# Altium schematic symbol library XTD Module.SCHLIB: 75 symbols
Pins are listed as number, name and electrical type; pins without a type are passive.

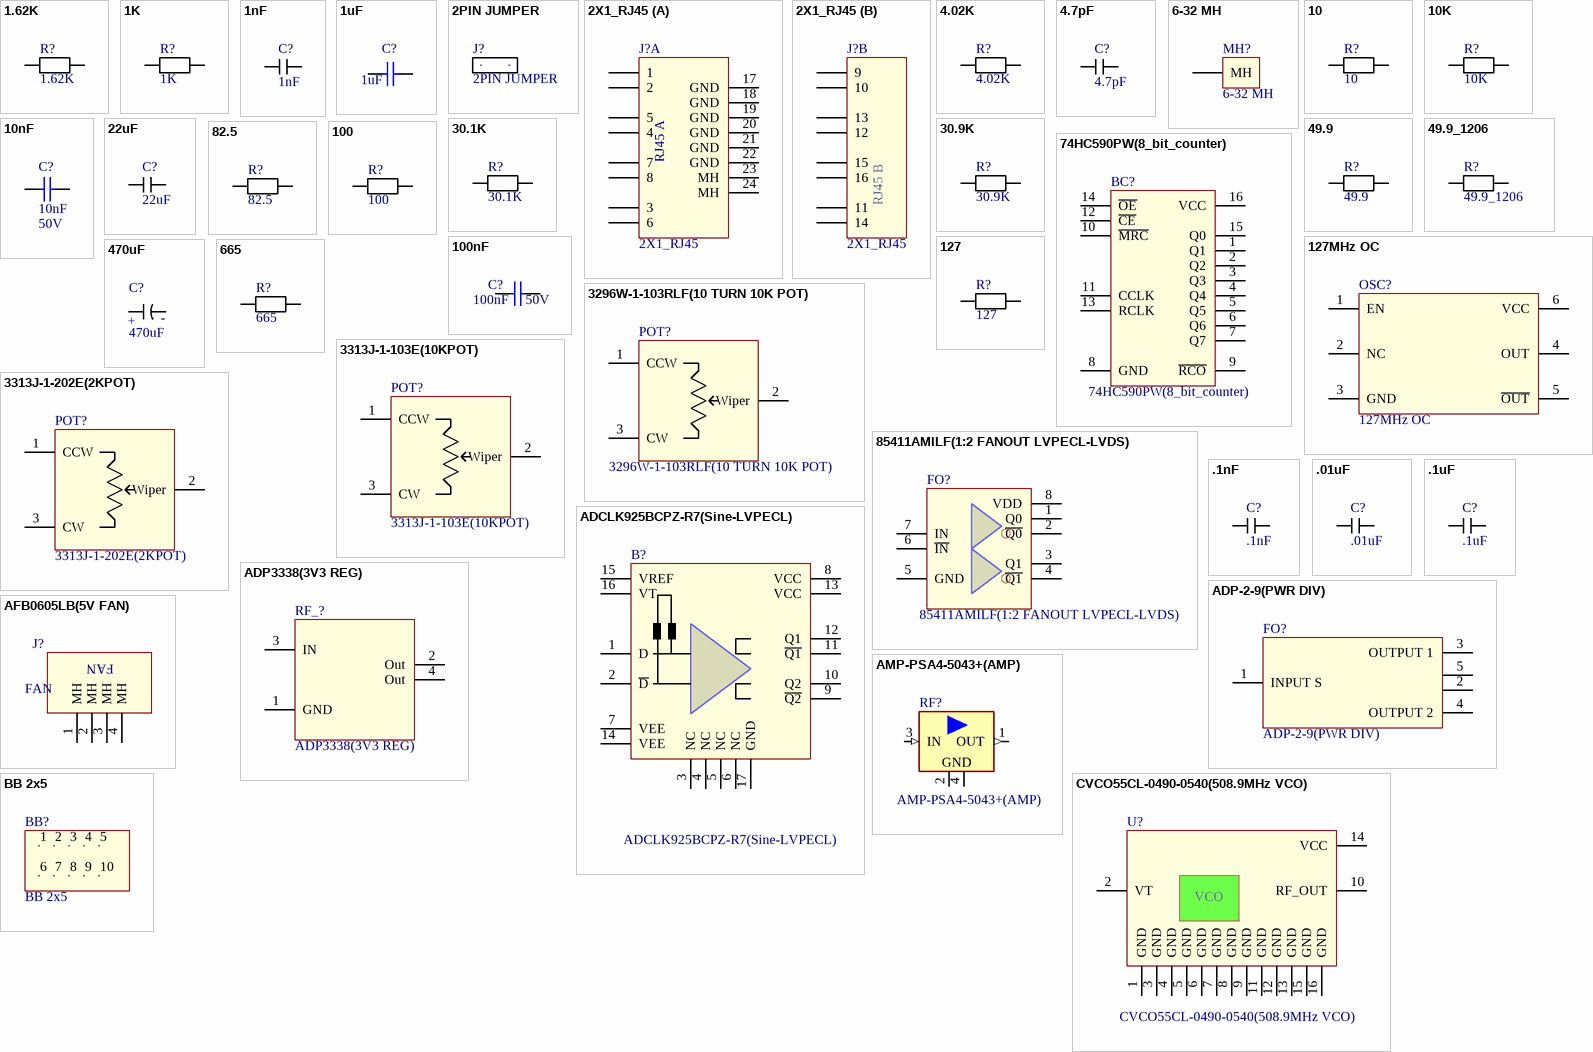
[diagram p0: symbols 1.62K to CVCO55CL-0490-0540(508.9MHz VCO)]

## 1.62K
designator R?
RES SMD 1.62K OHM 1% 1/16W 0402; Manufacturer: Samsung Electro-Mechanics America, Inc.; Manufacturer part #: RC1005F1621CS
footprint 0402 (0.039" L x 0.020" W (1.00mm x 0.50mm))
pins: 1, 2

## 1K
designator R?
RES SMD 1K OHM 5% 1/16W 0402; Manufacturer: Samsung Electro-Mechanics America, Inc.; Manufacturer part #: RC1005J102CS
footprint 0402 (0.039" L x 0.020" W (1.00mm x 0.50mm))
pins: 1, 2

## 1nF
designator C?
CAP CER 1000PF 50V X7R 0402; Manufacturer: Samsung Electro-Mechanics America, Inc.; Manufacturer part #: CL05B102KB5NNNC
footprint 0402 (0.039" L x 0.020" W (1.00mm x 0.50mm))
pins: 1, 2

## 1uF
designator C?
CAP CER 1UF 25V X7R 0603; Tech: SMDR; Voltage rating: 50V
signal-integrity model Model Name (Model Description)
footprint 0603 (0.063" L x 0.031" W (1.60mm x 0.80mm))
pins: 1, 2

## 2PIN JUMPER
designator J?
TWO PIN JUMPER
footprint 2 PIN HEADER
pins: 1, 2

## 2X1_RJ45
designator J?
CONN MOD JACK 8P8C R/A SHIELDED; Manufacturer: EDAC Inc.; Manufacturer part #: A00-216-672-450
footprint 2X1 RJ45 (DOUBLE_RIGHT ANGLE_RJ-45)
part A pins: 1, 2, 3, 4, 5, 6, 7, 8, 17 GND, 18 GND, 19 GND, 20 GND, 21 GND, 22 GND, 23 MH, 24 MH
part B pins: 9, 10, 11, 12, 13, 14, 15, 16

## 4.02K
designator R?
RES SMD 4.02K OHM 1% 1/16W 0402; Manufacturer: Samsung Electro-Mechanics America, Inc.; Manufacturer part #: RC1005F4021CS
footprint 0402 (0.039" L x 0.020" W (1.00mm x 0.50mm))
pins: 1, 2

## 4.7pF
designator C?
CAP CER 4.7PF 50V NP0 0603; Manufacturer: Samsung Electro-Mechanics America, Inc.; Manufacturer part #: CL10C4R7CB8NNNC
footprint 0603 (0.063" L x 0.031" W (1.60mm x 0.80mm))
pins: 1 "GROUND", 2

## 6-32 MH
designator MH?
6-32 MOUNTING HOLE
footprint 6-32 MH (6-32 MOUNTING HOLE)
pins: 1 MH

## 10
designator R?
RES SMD 10 OHM 5% 1/16W 0402; Manufacturer: Samsung Electro-Mechanics America, Inc.; Manufacturer part #: RC1005J100CS
footprint 0402 (0.039" L x 0.020" W (1.00mm x 0.50mm))
pins: 1, 2

## 10K
designator R?
RES SMD 10K OHM 5% 1/16W 0402; Manufacturer: Samsung Electro-Mechanics America, Inc.; Manufacturer part #: RC1005F4021CS
footprint 0402 (0.039" L x 0.020" W (1.00mm x 0.50mm))
pins: 1, 2

## 10nF
designator C?  Voltage rating: 50V
CAP CER 10000PF 50V X7R 0402; Manufacturer: Murata; Manufacturer No: GRM155R71H103KA88D; Tech: SMDR
footprint 0402 (0.039" L x 0.020" W (1.00mm x 0.50mm))
pins: 1, 2

## 22uF
designator C?
CAP CER 22UF 6.3V X5R 0603; Manufacturer: Samsung Electro-Mechanics America, Inc.; Manufacturer part #: CL10A226KQ8NRNE
footprint 0603 (0.063" L x 0.031" W (1.60mm x 0.80mm))
pins: 1 "GROUND", 2

## 30.1K
designator R?
RES SMD 30.1K OHM 1% 1/16W 0402; Manufacturer: Samsung Electro-Mechanics America, Inc.; Manufacturer part #: RC1005F3012CS
footprint 0402 (0.039" L x 0.020" W (1.00mm x 0.50mm))
pins: 1, 2

## 30.9K
designator R?
RES SMD 30.9K OHM 1% 1/10W 0402; Manufacturer: Panasonic Electronic Components; Manufacturer part #: ERJ-2RKF3092X
footprint 0402 (0.039" L x 0.020" W (1.00mm x 0.50mm))
pins: 1, 2

## 49.9
designator R?
RES SMD 49.9 OHM 1% 1/16W 0402; Manufacturer: Samsung Electro-Mechanics America, Inc.; Manufacturer part #: RC1005F49R9CS
footprint 0402 (0.039" L x 0.020" W (1.00mm x 0.50mm))
pins: 1, 2

## 49.9_1206
designator R?
RES SMD 49.9 OHM 1% 1/2W 1206; Manufacturer: Stackpole Electronics Inc.; Manufacturer part #: RNCP1206FTD49R9
footprint RC1206N1X (Chip resistor 1206)
pins: 1, 2

## 74HC590PW(8_bit_counter)
designator BC?
IC BINARY COUNTER 8BIT 16-TSSOP; Manufacturer: NXP Semiconductors; Manufacturer part #: 74HC590PW,118
footprint TSSOP_16pin (TSOP, 16-Leads, Body 5.00x4.40mm, Pitch 0.65mm, IPC Medium Density)
pins: 1 Q1, 2 Q2, 3 Q3, 4 Q4, 5 Q5, 6 Q6, 7 Q7, 8 GND, 9 ~{RCO}, 10 ~{MRC}, 11 CCLK, 12 ~{CE}, 13 RCLK, 14 ~{OE}, 15 Q0, 16 VCC

## 82.5
designator R?
RES SMD 82.5 OHM 1% 1/16W 0402; Manufacturer: Samsung Electro-Mechanics America, Inc.; Manufacturer part #: RC1005F82R5CS
footprint 0402 (0.039" L x 0.020" W (1.00mm x 0.50mm))
pins: 1, 2

## 100
designator R?
RES SMD 100 OHM 5% 1/16W 0402; Manufacturer: Samsung Electro-Mechanics America, Inc.; Manufacturer part #: RC1005J101CS
footprint 0402 (0.039" L x 0.020" W (1.00mm x 0.50mm))
pins: 1, 2

## 100nF
designator C?  Voltage rating: 50V
Capacitor chip ceramic 0402 50V X7R; Manufacturer: TDK; Manufacturer No: C1005X7R1H104K050BB; Tech: SMDR
signal-integrity model Model Name (Model Description)
footprint 0402 (0.039" L x 0.020" W (1.00mm x 0.50mm))
pins: 1, 2

## 127
designator R?
RES SMD 127 OHM 1% 1/16W 0402; Manufacturer: Samsung Electro-Mechanics America, Inc.; Manufacturer part #: RC1005F1270CS
footprint 0402 (0.039" L x 0.020" W (1.00mm x 0.50mm))
pins: 1, 2

## 127MHz OC
designator OSC?
OSC VCO 127.21MHZ
footprint 127MHz OC
pins: 1 EN "ENABLE/DISABLE", 2 NC, 3 GND "GROUND", 4 OUT "NONEINVERTED OUTPUT", 5 ~{OUT} "INVERTED OUTPUT", 6 VCC "POWER INPUT"

## 470uF
designator C?
CAP ALUM 470UF 20% 50V RADIAL; Manufacturer: Nichicon; Manufacturer part #: UPW1H471MHD
footprint CAP_TH
pins: 1 "GROUND", 2

## 665
designator R?
RES SMD 665 OHM 1% 1/16W 0402; Manufacturer: Samsung Electro-Mechanics America, Inc.; Manufacturer part #: RC1005F6650CS
footprint 0402 (0.039" L x 0.020" W (1.00mm x 0.50mm))
pins: 1, 2

## 3296W-1-103RLF(10 TURN 10K POT)
designator POT?
TRIMMER 10K OHM 0.5W PC PIN; Manufacturer: Bourns Inc.
footprint 10K POT (TRIMMER 10K OHM 0.5W PC PIN)
pins: 1 CCW "Control Votage", 2 Wiper "Ground", 3 CW "Supply Voltage"

## 3313J-1-103E(10KPOT)
designator POT?
TRIMMER 10K OHM 0.125W SMD; Manufacturer: Bourns Inc.
footprint 2KPOT (TRIMMER 2K OHM 0.125W SMD)
pins: 1 CCW "Control Votage", 2 Wiper "Ground", 3 CW "Supply Voltage"

## 3313J-1-202E(2KPOT)
designator POT?
TRIMMER 2K OHM 0.125W SMD; Manufacturer: Bourns Inc.
footprint 2KPOT (TRIMMER 2K OHM 0.125W SMD)
pins: 1 CCW "Control Votage", 2 Wiper "Ground", 3 CW "Supply Voltage"

## 85411AMILF(1:2 FANOUT LVPECL-LVDS)
designator FO?
IC CLK BUFFER 1:2 650MHZ 8SOIC; Manufacturer: IDT, Integrated Device Technology Inc
footprint SOIC_8pin (SOIC, 8-Leads, Body 5.00x4.00mm, Pitch 1.27mm, IPC Medium Density)
pins: 1 Q0, 2 ~{Q0}, 3 Q1, 4 ~{Q1}, 5 GND, 6 ~{IN}, 7 IN, 8 VDD

## .1nF
designator C?
CAP CER 100PF 50V NP0 0603; Manufacturer: Samsung Electro-Mechanics America, Inc.; Manufacturer part #: CL10C101JB8NNNC
footprint 0603 (0.063" L x 0.031" W (1.60mm x 0.80mm))
pins: 1 "GROUND", 2

## .01uF
designator C?
CAP CER 10000PF 50V X7R 0603; Manufacturer: Samsung Electro-Mechanics America, Inc.; Manufacturer part #: CL10B103KB8NCNC
footprint 0603 (0.063" L x 0.031" W (1.60mm x 0.80mm))
pins: 1 "GROUND", 2

## .1uF
designator C?
CAP CER 0.1UF 50V X7R 0603; Manufacturer: Samsung Electro-Mechanics America, Inc.; Manufacturer part: CL10B104KB8SFNC
footprint 0603 (0.063" L x 0.031" W (1.60mm x 0.80mm))
pins: 1 "GROUND", 2

## ADCLK925BCPZ-R7(Sine-LVPECL)
designator B?
IC CLK BUFFER 1:2 7.5GHZ 16LFCSP; Manufacturer: Analog Devices Inc.
footprint QFN_16pin (QFN, 16-Leads, Body 3.00x3.00mm, Pitch 0.50mm, Thermal Pad 1.50x1.50mm, IPC Medium Density)
pins: 1 D "Noninverting Input", 2 ~{D} "Inverting Input", 3 NC "No Connect", 4 NC "No Connect", 5 NC "No Connect", 6 NC "No Connect", 7 VEE "Negative Supply Voltage.", 8 VCC "Positive Supply Voltage.", 9 ~{Q2} "Inverting Output 2.", 10 Q2 "Noninverting Output 2.", 11 ~{Q1} "Inverting Output 1.", 12 Q1 "Noninverting Output 1.", 13 VCC "Positive Supply Voltage.", 14 VEE "Negative Supply Voltage.", 15 VREF "Reference Voltage.", 16 VT "Center Tap. Center tap of 100 Ω input resistor.", 17 GND "Center Tap. Center tap of 100 Ω input resistor."

## ADP3338(3V3 REG)
designator RF_?
IC REG LDO 3.3V 1A SOT223-3; Manufacturer: Analog Devices Inc; Manufacturer part #: ADP3338AKCZ-3.3RL7
footprint ADP3338 (SOT223, 4-Leads, Body 6.50x7.00mm (avg), Pitch 2.30mm, IPC Medium Density)
footprint ADP3338 (SOT223, 4-Leads, Body 6.50x7.00mm (avg), Pitch 2.30mm, IPC Medium Density)
pins: 1 GND "Ground", 2 Out "Output", 3 IN "Input", 4 Out "Output"

## ADP-2-9(PWR DIV)
designator FO?
PWR SPL CMB / SM / RoHS5; Manufacturer: MINI_CIRCUITS
footprint PWR SPLITTER (SOTFL, 6-Leads, Body 7.87x6.91mm, Pitch 2.54mm, IPC Medium Density)
pins: 1 INPUT S "INPUT", 2 OUTPUT 4 "Externally connect together & isolate", 3 OUTPUT 1 "OUTPUT", 4 OUTPUT 2 "OUTPUT", 5 OUTPUT 3 "Externally connect together & isolate"

## AFB0605LB(5V FAN)
designator J?, comment FAN
FAN AXIAL 60X15MM BALL 5VDC WIRE; Manufacturer: Delta Electronics; Manufacturer part #: AFB0605LB
footprint FAN (FAN AXIAL 60X15MM BALL 5VDC WIRE)
pins: 1 MH, 2 MH, 3 MH, 4 MH

## AMP-PSA4-5043+(AMP)
designator RF?
Monolithic Amplifier 50MHz - 4GHz, 0.75NF; Manufacturer: MiniCircuits; Tech: SMDR
footprint MMM1362
pins: 1 OUT (out), 2 GND (power), 3 IN (in), 4 GND (power)

## BB 2x5
designator BB?
footprint BREAD BOARD (2X5 .1IN BREAD BAORD)
pins: 1 "POSITIVE GROUND", 2 "POSITIVE GROUND", 3 "POSITIVE GROUND", 4 "POSITIVE GROUND", 5 "POSITIVE GROUND", 6 "POSITIVE GROUND", 7 "POSITIVE GROUND", 8 "POSITIVE GROUND", 9 "POSITIVE GROUND", 10 "POSITIVE GROUND"

## CVCO55CL-0490-0540(508.9MHz VCO)
designator U?
OSC VCO 490-540MHZ SMD .5X.5"; Manufacturer: ON Semiconductor
footprint QFN_16pin Variant (QFN, 16-Leads, Body 12.70x12.70mm, Pitch 2.54mm, Variant)
pins: 1 GND "Regulator Input Supply.", 2 VT "Control voltage", 3 GND "Regulator Input Supply.", 4 GND "Regulator Input Supply.", 5 GND "Regulator Input Supply.", 6 GND "Regulator Input Supply.", 7 GND "Regulator Input Supply.", 8 GND "Regulator Input Supply.", 9 GND "Regulator Input Supply.", 10 RF_OUT "RF OUTPUT", 11 GND "Regulator Input Supply.", 12 GND "Regulator Input Supply.", 13 GND "Regulator Input Supply.", 14 VCC "Positive power pin", 15 GND "Regulator Input Supply.", 16 GND "Regulator Input Supply."

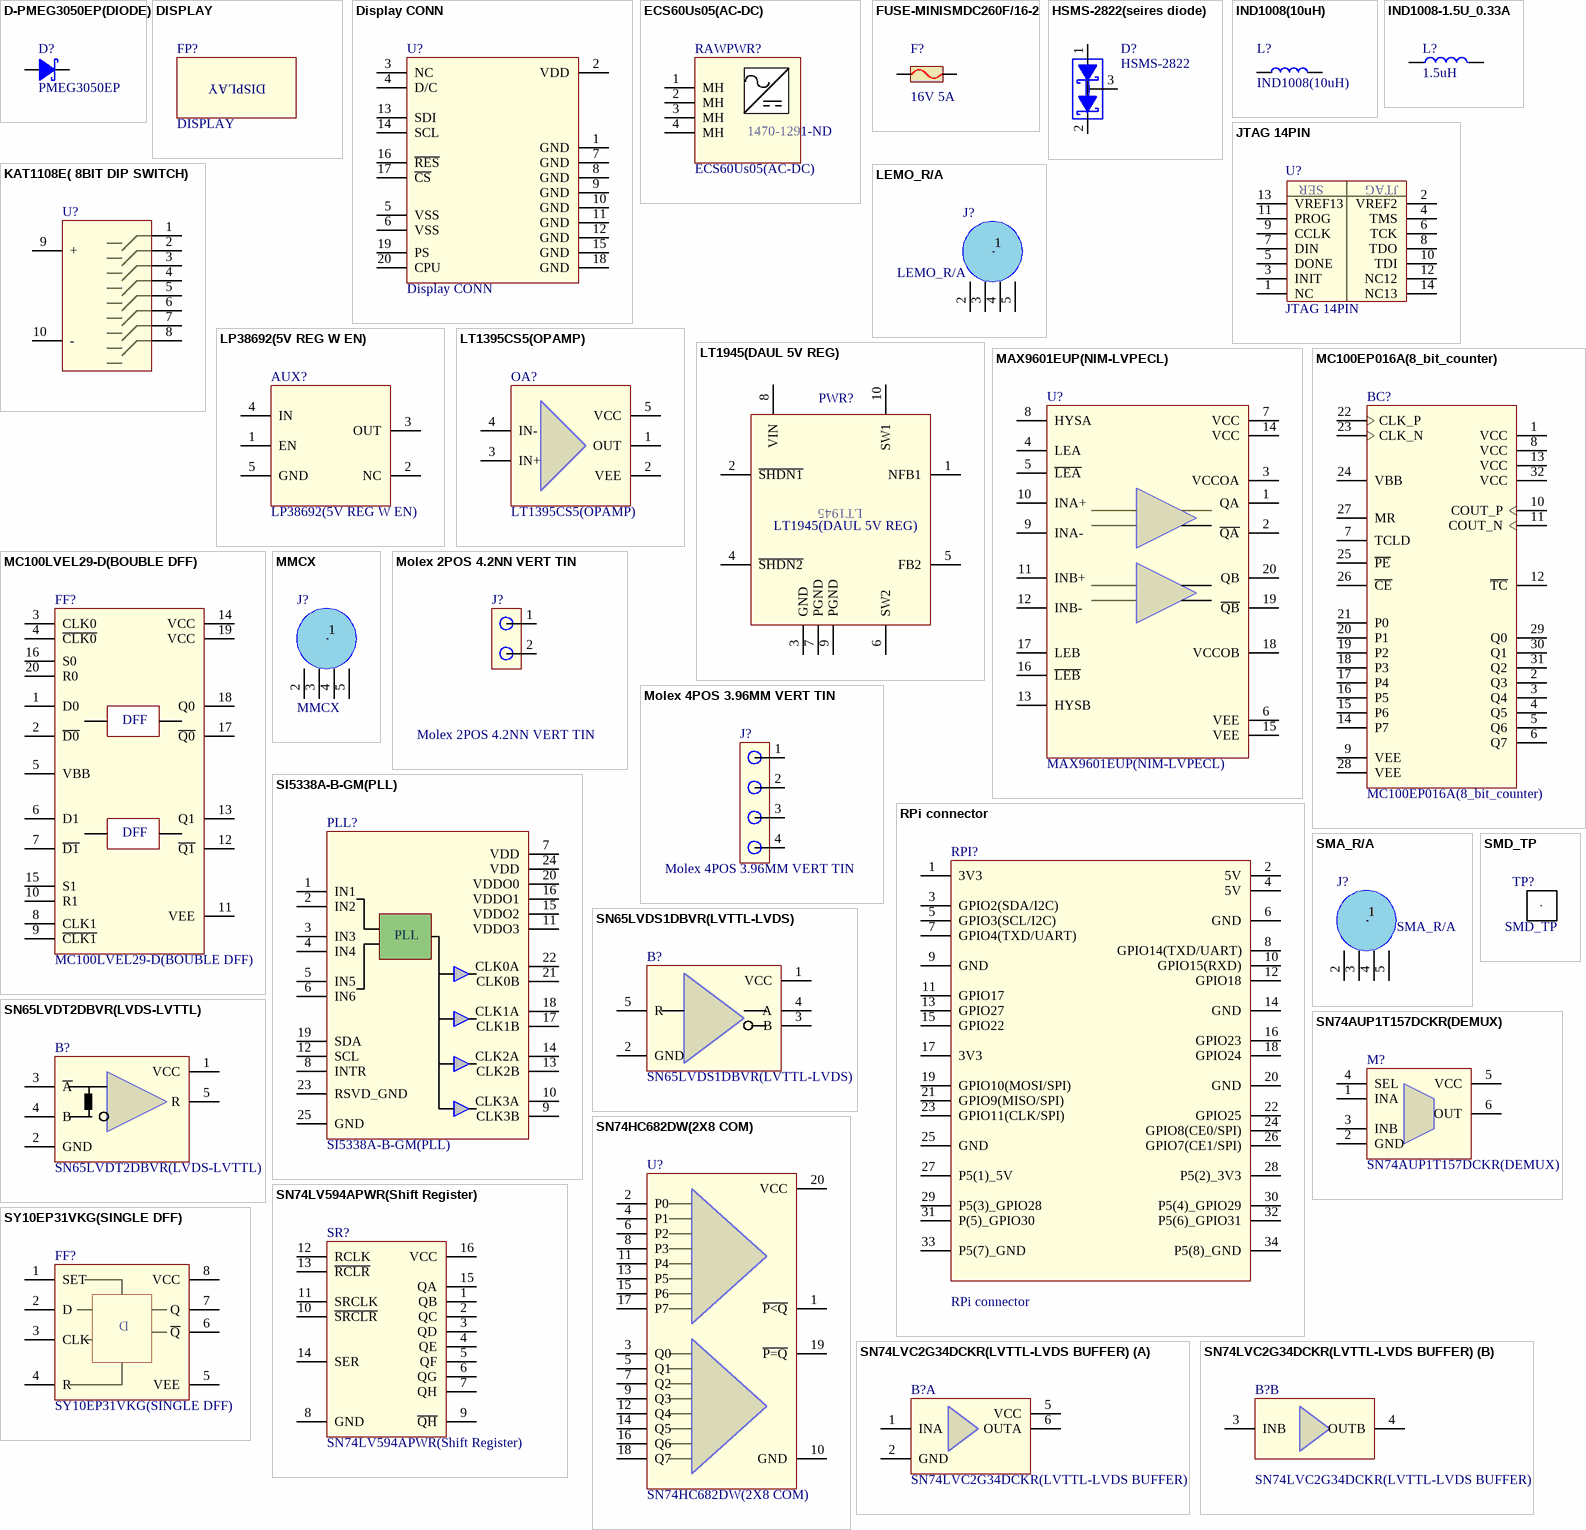
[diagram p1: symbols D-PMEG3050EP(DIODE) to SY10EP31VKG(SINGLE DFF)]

## D-PMEG3050EP(DIODE)
designator D?, comment PMEG3050EP
Schottky diode 6A 30V 500ns 0.36Vf; Manufacturer: NXP; Manufacturer No: PMEG3050EP,115; Tech: SMDR
footprint SOD128
pins: 1 C, 2 A

## DISPLAY
designator FP?
DOUBLE NIM FRONT PANEL
footprint DISPLAY

## Display CONN
designator U?
DISPLAY FULL COLOR OLED 1.69"; Manufacturer: Newhaven Display Intl; Manufacturer part #: NHD-1.69-160128UGC3
footprint DISPLAY CONN (DISPLAY)
pins: 1 GND "GROUND", 2 VDD "GROUND", 3 NC "GROUND", 4 D/C, 5 VSS, 6 VSS, 7 GND "GROUND", 8 GND "GROUND", 9 GND "GROUND", 10 GND "GROUND", 11 GND "GROUND", 12 GND "GROUND", 13 SDI, 14 SCL, 15 GND "GROUND", 16 ~{RES}, 17 ~{CS}, 18 GND "GROUND", 19 PS, 20 CPU

## ECS60Us05(AC-DC)
designator RAWPWR?  Digikey #: 1470-1291-ND
AC-DC convertor; Manufacturer: XP Power
footprint ECS60US05 (AC-DC Convertor, 5V at 8A)
footprint ECS60US05 (AC-DC Convertor, 5V at 8A)
pins: 1 MH, 2 MH, 3 MH, 4 MH

## FUSE-MINISMDC260F/16-2
designator F?, comment 16V 5A
PolySwitch Fuse SMD 1812 16V 5A; Manufacturer: TE Connectivity; Manufacturer No: MINISMDC260F/16-2; Tech: SMDR
footprint FUSE4532-1
pins: 1, 2

## HSMS-2822(seires diode)
designator D?, comment HSMS-2822
Surface Mount RF Schottky Barrier Diodes, Series Config.; Manufacturer: Avago; Manufacturer No: HSMS-2822-TR1G; Tech: SMDR
footprint SOT23_3pin (SOT23, 3-Leads, Body 3.00x2.50mm, Pitch 1.00mm, IPC Medium Density)
pins: 1 A1, 2 C2, 3 C1A2

## IND1008(10uH)
designator L?
FIXED IND 10UH 520MA 854 MOHM; Manufacturer: TDK Corporation; Manufacturer part #: VLS252010T-100M
footprint 1008 (0.098" L x 0.079" W (2.50mm x 2.00mm))
pins: 1, 2

## IND1008-1.5U_0.33A
designator L?, comment 1.5uH
Chip inductor 1008 0.33A 2.3R; Manufacturer: Coilcraft; Manufacturer No: 1008CS-152XJLB; Tech: SMDR
signal-integrity model Model Name (Model Description)
footprint 1008 (0.098" L x 0.079" W (2.50mm x 2.00mm))
pins: 1, 2

## JTAG 14PIN
designator U?
CONN HEADER 14POS 2MM GOLD DIP; Manufacturer: Hirose Electric Co Ltd; Manufacturer part #: A3C-14P-2DSA
footprint JTAG_14PIN_2MM_VERT
pins: 1 NC "GROUND", 2 VREF2 "GROUND", 3 INIT "GROUND", 4 TMS "GROUND", 5 DONE "GROUND", 6 TCK "GROUND", 7 DIN "GROUND", 8 TDO "GROUND", 9 CCLK "GROUND", 10 TDI "GROUND", 11 PROG "GROUND", 12 NC12 "GROUND", 13 VREF13 "GROUND", 14 NC13 "GROUND"

## KAT1108E( 8BIT DIP SWITCH)
designator U?
DIP SW 8POS EXTEND ACTUATOR 24V; Manufacturer: Samsung Electro-Mechanics America, Inc.; Manufacturer part #: CL10B103KB8NCNC
footprint 8 BIT DIP SWITCH (24.30mm X 10mm X 6.70mm PITHC 2.54mm)
pins: 1 11 "BIT 1", 2 12 "BIT 2", 3 13 "BIT 3", 4 14 "BIT 4", 5 15 "BIT 5", 6 16 "BIT 6", 7 17 "BIT 7", 8 18 "BIT 8", 9 + "GROUND", 10 - "POWER"

## LEMO_R/A
designator J?
CONN JACK R/A 50 OHM PCB; Manufacturer: LEMO; Manufacturer part #: EPL.00.250.NTN
footprint LEMO_R/A (EPA.00.250.NTN, RIGHT ANGLE)
pins: 1, 2, 3 "INPUT", 4 "INPUT", 5 "INPUT"

## LP38692(5V REG W EN)
designator AUX?
IC REG LDO 5V 0.5A SOT223-5; Manufacturer: Texas Instruments; Manufacturer part #: LP38692MPX-5.0/NOPBCT-ND
footprint SOT223_5pin (SOT223, 5-Leads, Body 6.50x7.00mm (avg), Pitch 1.50mm, IPC Medium Density)
pins: 1 EN "ENABLE/DISABLE", 2 NC, 3 OUT "OUTPUT", 4 IN "INPUT", 5 GND "GROUND"

## LT1395CS5(OPAMP)
designator OA?
IC OPAMP CFA 400MHZ TSOT23-5; Manufacturer: Linear Technology; Manufacturer part #: LT1395CS5#TRMPBF
footprint SOT23_5PIN (SOT23, 5-Leads, Body 3.00x2.80mm, Pitch 1.00mm, IPC Medium Density)
pins: 1 OUT, 2 VEE, 3 IN+, 4 IN-, 5 VCC

## LT1945(DAUL 5V REG)
designator PWR?
IC REG BST SEPIC INV ADJ 10MSOP; Manufacturer: Linear Technology; Manufacturer part #: LT1945EMS#PBF
footprint TFSOP_10pin (TSSOP, 10-Leads, Body 3.00x3.00mm, Pitch 0.50mm, IPC Medium Density)
pins: 1 NFB1 "NAGATIVE FEDDBACK", 2 ~{SHDN1} "SHUT DOWN", 3 GND "GROUND", 4 ~{SHDN2} "SHUT DOWN 2", 5 FB2 "FEEDBACK 2", 6 SW2 "FEEDBACK 2", 7 PGND "POSITIVE GROUND", 8 VIN "INPUT POWER", 9 PGND "POSITIVE GROUND", 10 SW1 "POSITIVE GROUND"

## MAX9601EUP(NIM-LVPECL)
designator U?
IC COMPARATOR HS 20-TSSOP; Manufacturer: Maxim Integrated; Manufacturer part #: MAX9601EUP+
footprint TSSOP_20pin (TSOP, 20-Leads, Body 6.50x4.50mm, Pitch 0.65mm, IPC Medium Density)
pins: 1 QA "Channel A Output", 2 ~{QA} "Channel A Complementary Output", 3 VCCOA "Channel A Output Driver Positive Supply", 4 LEA "Channel A Latch-Enable Input", 5 ~{LEA} "Channel A Latch-Enable Input", 6 VEE "Negative Supply Voltage", 7 VCC "Positive Supply Voltage", 8 HYSA "Channel A Hysteresis Input", 9 INA- "Channel A Minus Input", 10 INA+ "Channel A Plus Input", 11 INB+ "Channel B Plus Input", 12 INB- "Channel B Minus Input", 13 HYSB "Channel B Hysteresis Input", 14 VCC "Positive Supply Voltage", 15 VEE "Negative Supply Voltage", 16 ~{LEB} "Channel B Latch-Enable Input", 17 LEB "Channel B Latch-Enable Input", 18 VCCOB "Channel B Output Driver Positive Supply", 19 ~{QB} "Channel B Complementary Output", 20 QB "Channel B Output"

## MC100EP016A(8_bit_counter)
designator BC?
IC COUNTER 8BIT SYNC ECL 32LQFP; Manufacturer: ON Semiconductor; Manufacturer part #: MC100EP016AFAG
footprint LQFP_32pin (LQFP, 32-Leads, Body 7.00x7.00mm, Pitch 0.80mm, IPC Medium Density)
pins: 1 VCC "Positive Supply", 2 Q3 "ECL Data Outputs", 3 Q4 "ECL Data Outputs", 4 Q5 "ECL Data Outputs", 5 Q6 "ECL Data Outputs", 6 Q7 "ECL Data Outputs", 7 TCLD "ECL TC-Load Control Input (Pins will default LOW when left open)", 8 VCC "Positive Supply", 9 VEE "Negative Supply", 10 COUT_P "ECL Differential Output", 11 COUT_N "ECL Differential Output", 12 ~{TC} "ECL Terminal Count Output", 13 VCC "Positive Supply", 14 P7 "ECL Parallel Data (Preset) Inputs", 15 P6 "ECL Parallel Data (Preset) Inputs", 16 P5 "ECL Parallel Data (Preset) Inputs", 17 P4 "ECL Parallel Data (Preset) Inputs", 18 P3 "ECL Parallel Data (Preset) Inputs", 19 P2 "ECL Parallel Data (Preset) Inputs", 20 P1 "ECL Parallel Data (Preset) Inputs", 21 P0 "ECL Parallel Data (Preset) Inputs", 22 CLK_P "ECL Differential Clock", 23 CLK_N (hiz) "ECL Differential Clock", 24 VBB "Reference Voltage Output", 25 ~{PE} "ECL Parallel Load Enable Control Input (Pins will default LOW when left open)", 26 ~{CE} "ECL Count Enable Control Input (Pins will default LOW when left open)", 27 MR "ECL Master Reset (Pins will default LOW when left open)", 28 VEE "Negative Supply", 29 Q0 "ECL Data Outputs", 30 Q1 "ECL Data Outputs", 31 Q2 "ECL Data Outputs", 32 VCC "Positive Supply"

## MC100LVEL29-D(BOUBLE DFF)
designator FF?
IC D-TYPE POS TRG DUAL 20SOIC; Manufacturer: ON Semiconductor; Manufacturer part #: MC100LVEL29DWG
footprint SOIC_20pin (SOIC, 20-Leads, Body 12.80x7.50mm, Pitch 1.27mm, IPC Medium Density)
pins: 1 D0 "ECL Differential Data Inputs", 2 ~{D0} "ECL Differential Data Inputs", 3 CLK0 "ECL Differential Clock Inputs", 4 ~{CLK0} "ECL Differential Clock Inputs", 5 VBB "Reference Voltage Output", 6 D1 "ECL Differential Data Inputs", 7 ~{D1} "ECL Differential Data Inputs", 8 CLK1 "ECL Differential Clock Inputs", 9 ~{CLK1} "ECL Differential Clock Inputs", 10 R1 "ECL Reset Inputs", 11 VEE "Negative Supply", 12 ~{Q1} "ECL Differential Data Outputs", 13 Q1 "ECL Differential Data Outputs", 14 VCC "Positive Supply", 15 S1 "ECL Set Inputs", 16 S0 "ECL Set Inputs", 17 ~{Q0} "ECL Differential Data Outputs", 18 Q0 "ECL Differential Data Outputs", 19 VCC "Positive Supply", 20 R0 "ECL Reset Inputs"

## MMCX
designator J?
CONN MMCX JACK STR 50 OHM PCB; Manufacturer: Molex, LLC; Manufacturer part #: 0734151471
footprint MMCX_VERTICAL_THROUGH_HOLE
pins: 1, 2, 3 "INPUT", 4 "INPUT", 5 "INPUT"

## Molex 2POS 4.2NN VERT TIN
designator J?
CONN HEADER 2POS 4.2MM VERT TIN; Manufacturer: Molex Inc.; Manufacturer part #: 0009652048
footprint Molex 2POS (CONN HEADER 2POS 4.2MM VERT TIN)
pins: 1 "Ground", 2 "Output"

## Molex 4POS 3.96MM VERT TIN
designator J?
CONN HEADER 4POS 3.96MM VERT TIN; Manufacturer: Molex Inc.; Manufacturer part #: 0009652048
footprint Molex 4POS (CONN HEADER 4POS 3.96MM VERT TIN)
footprint Molex 4POS (CONN HEADER 4POS 3.96MM VERT TIN)
pins: 1 "Ground", 2 "Output", 3 "Input", 4 "Input"

## RPi connector
designator RPI?
Rpi
footprint RPi (connector for RPi)
pins: 1 3V3 "External Reset", 2 5V "Frequency Table.", 3 GPIO2(SDA/I2C) "CKIN Loss of Signal.", 4 5V "No Connect", 5 GPIO3(SCL/I2C) "Supply.", 6 GND "External Crystal or Reference Clock.", 7 GPIO4(TXD/UART) "External Crystal or Reference Clock.", 8 GPIO14(TXD/UART) "Ground.", 9 GND "No Connect", 10 GPIO15(RXD) "Supply.", 11 GPIO17 "External Crystal or Reference Clock Rate.", 12 GPIO18 "No Connect", 13 GPIO27 "No Connect", 14 GND "Output 2 Disable/Bypass Mode Control", 15 GPIO22 "External Crystal or Reference Clock Rate.", 16 GPIO23 "Clock Input.", 17 3V3 "Clock Input.", 18 GPIO24 "PLL Loss of Lock Indicator.", 19 GPIO10(MOSI/SPI) "Skew Decrement", 20 GND "Skew Increment.", 21 GPIO9(MISO/SPI) "No Connect", 22 GPIO25 "Loop Bandwidth Select.", 23 GPIO11(CLK/SPI) "Loop Bandwidth Select.", 24 GPIO8(CE0/SPI) "Frequency Select.", 25 GND "Frequency Select.", 26 GPIO7(CE1/SPI) "Frequency Select.", 27 P5(1)_5V "Frequency Select.", 28 P5(2)_3V3 "Clock Output 1", 29 P5(3)_GPIO28 "Clock Output 1", 30 P5(4)_GPIO29 "Signal Format Select.", 31 P(5)_GPIO30 "Ground.", 32 P5(6)_GPIO31 "Supply.", 33 P5(7)_GND "Signal Format Select.", 34 P5(8)_GND "Clock Output 2."

## SI5338A-B-GM(PLL)
designator PLL?
IC CLK GEN I2C BUS PROG 24QFN; Manufacturer: Silicon Labs
footprint QFN_24pin (QFN, 24-Leads, Body 4.00x4.00mm, Pitch 0.50mm, Thermal Pad 2.50x2.50mm, IPC Medium Density)
pins: 1 IN1 "CLKIN/CLKB", 2 IN2 "Complimentery CLKIN/CLKB", 3 IN3 "Single ended input.", 4 IN4 "Single ended input.", 5 IN5 "FDBK/FDBKB", 6 IN6 "Complimentery FDBK/FDBKB", 7 VDD "Core Supply Voltage.", 8 INTR "Interrupt.", 9 CLK3B "Output Clock B for Channel 3.", 10 CLK3A "Output Clock A for Channel 3.", 11 VDDO3 "Output Clock Supply Voltage.", 12 SCL "I2C Serial Clock Input.", 13 CLK2B "Output Clock B for Channel 2.", 14 CLK2A "Output Clock A for Channel 2.", 15 VDDO2 "Output Clock Supply Voltage.", 16 VDDO1 "Output Clock Supply Voltage.", 17 CLK1B "Output Clock B for Channel 1.", 18 CLK1A "Output Clock A for Channel 1", 19 SDA "I2C Serial Data.", 20 VDDO0 "Output Clock Supply Voltage.", 21 CLK0B "Output Clock B for Channel 0.", 22 CLK0A "Output Clock A for Channel 0", 23 RSVD_GND "Ground", 24 VDD "Core Supply Voltage", 25 GND "Core Supply Voltage"

## SMA_R/A
designator J?
CONN SMA JACK R/A 50 OHM PCB; Manufacturer: Molex, LLC; Manufacturer part #: 0732512201
footprint SMA_R/A (Panel Mount, Bulkhead; Through Hole,RIGHT ANGLE)
pins: 1, 2, 3 "INPUT", 4 "INPUT", 5 "INPUT"

## SMD_TP
designator TP?
SURFACE MOUNT TEST POINT
footprint SMD_TP (SURFACE MOUNT TEST PAD)
pins: 1 TP "test point"

## SN65LVDS1DBVR(LVTTL-LVDS)
designator B?
IC HIGH DIFF LINE DRIVER SOT23-5; Manufacturer: Texas Instruments
footprint SOT23_5PIN (SOT23, 5-Leads, Body 3.00x2.80mm, Pitch 1.00mm, IPC Medium Density)
pins: 1 VCC, 2 GND, 3 B "Noninverting Input", 4 A "Inverting Input", 5 R

## SN65LVDT2DBVR(LVDS-LVTTL)
designator B?
IC DIFF LINE RECEIVER SOT-23-5; Manufacturer: Texas Instruments
footprint SOT23_5PIN (SOT23, 5-Leads, Body 3.00x2.80mm, Pitch 1.00mm, IPC Medium Density)
pins: 1 VCC, 2 GND, 3 ~{A} "Noninverting Input", 4 B "Inverting Input", 5 R

## SN74AUP1T157DCKR(DEMUX)
designator M?
IC BUFF/MUX SCHMITT-TRIG SC70-6; Manufacturer: Texas Instruments
footprint TSSOP_6PIN (TSOP, 6-Leads, Body 2.15x1.40mm, Pitch 0.65mm, IPC Medium Density)
pins: 1 INA, 2 GND, 3 INB, 4 SEL, 5 VCC, 6 OUT

## SN74HC682DW(2X8 COM)
designator U?
IC COMPARATOR MAGNITUDE 20SOIC; Manufacturer: Texas Instruments
footprint SOIC_20pin (SOIC, 20-Leads, Body 12.80x7.50mm, Pitch 1.27mm, IPC Medium Density)
pins: 1 ~{P<Q} "OUTPUT", 2 P0 "OUTPUT", 3 Q0 "OUTPUT", 4 P1 "OUTPUT", 5 Q1 "OUTPUT", 6 P2 "OUTPUT", 7 Q2 "OUTPUT", 8 P3 "OUTPUT", 9 Q3 "OUTPUT", 10 GND "OUTPUT", 11 P4 "OUTPUT", 12 Q4 "OUTPUT", 13 P5 "OUTPUT", 14 Q5 "OUTPUT", 15 P6 "OUTPUT", 16 Q6 "OUTPUT", 17 P7 "OUTPUT", 18 Q7 "OUTPUT", 19 ~{P=Q} "OUTPUT", 20 VCC "OUTPUT"

## SN74LV594APWR(Shift Register)
designator SR?
IC 8-BIT SHFT REG W/OUT 16-TSSOP; Manufacturer: Texas Instruments
footprint TSSOP_16pin (TSOP, 16-Leads, Body 5.00x4.40mm, Pitch 0.65mm, IPC Medium Density)
pins: 1 QB "Output B", 2 QC "Output C", 3 QD "Output D", 4 QE "Output E", 5 QF "Output F", 6 QG "Output G", 7 QH "Output H", 8 GND "GROUND", 9 ~{QH} "QH inverted", 10 ~{SRCLR} "Serial clear", 11 SRCLK "Serial clock", 12 RCLK "Storage clock", 13 ~{RCLR} "Stroage clear", 14 SER "Serial input", 15 QA "Output A", 16 VCC "power pin."

## SN74LVC2G34DCKR(LVTTL-LVDS BUFFER)
designator B?
IC BUFFER DUAL NON-INV SC706; Manufacturer: Texas Instruments
footprint TSSOP_6PIN (TSOP, 6-Leads, Body 2.15x1.40mm, Pitch 0.65mm, IPC Medium Density)
part A pins: 1 INA, 2 GND, 5 VCC, 6 OUTA
part B pins: 3 INB, 4 OUTB

## SY10EP31VKG(SINGLE DFF)
designator FF?
IC D-TYPE POS TRG SNGL 8MSOP; Manufacturer: Micrel Inc.
footprint MSOP8N
pins: 1 SET "CLOCK INPUT", 2 D "J INPUT", 3 CLK "K INPUT", 4 R "RESET", 5 VEE "GROUND", 6 ~{Q} "INVERTED OUTPUT", 7 Q "NONINVERTED OUTPUT", 8 VCC "POWER"

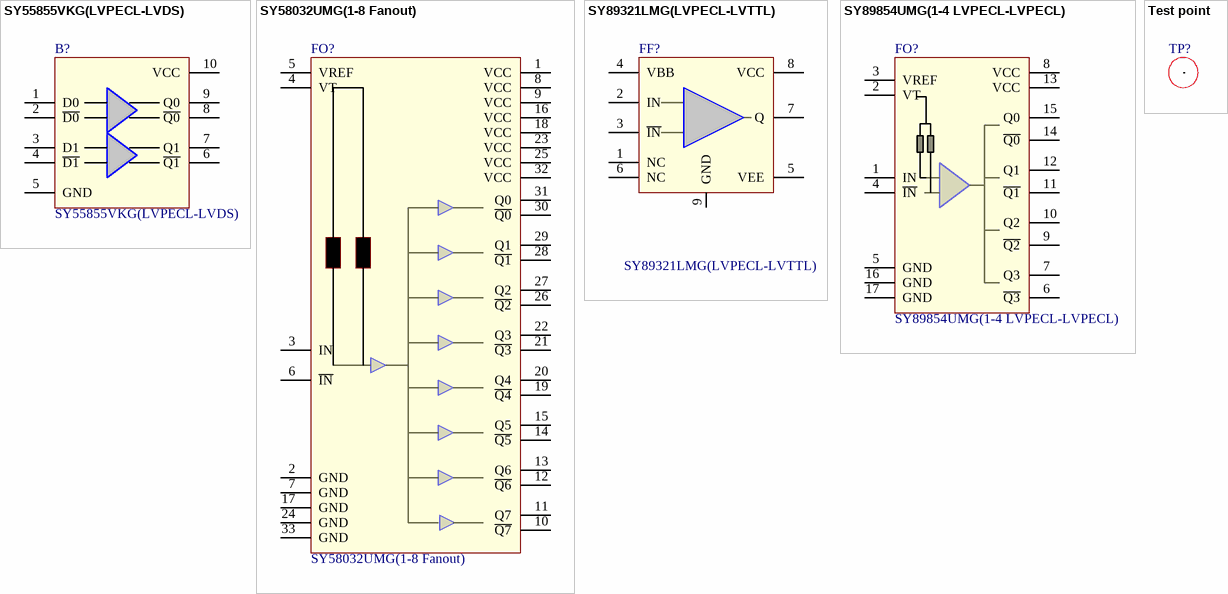
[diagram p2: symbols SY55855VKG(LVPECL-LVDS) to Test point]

## SY55855VKG(LVPECL-LVDS)
designator B?
IC TRANSLATOR DUAL LVDS 10MSOP; Manufacturer: Micrel Inc.
footprint TFSOP_10pin (TSSOP, 10-Leads, Body 3.00x3.00mm, Pitch 0.50mm, IPC Medium Density)
pins: 1 D0 "CML/PECL/LVPECL Input (Differential)", 2 ~{D0} "CML/PECL/LVPECL Input (Differential)", 3 D1 "CML/PECL/LVPECL Input (Differential)", 4 ~{D1} "CML/PECL/LVPECL Input (Differential)", 5 GND "Ground.", 6 ~{Q1} "LVDS Output (Differential)", 7 Q1 "LVDS Output (Differential)", 8 ~{Q0} "LVDS Output (Differential)", 9 Q0 "LVDS Output (Differential)", 10 VCC "Positive input."

## SY58032UMG(1-8 Fanout)
designator FO?
IC CLK BUFFER 1:8 4GHZ 32MLF; Manufacturer: Micrel Inc.
footprint MLF_QFN_32PIN (PQFN, 32-Leads, Body 5.00x5.00mm, Pitch 0.50mm, Thermal Pad 3.10x3.10mm, IPC Medium Density)
pins: 1 VCC, 2 GND, 3 IN, 4 VT, 5 VREF, 6 ~{IN}, 7 GND, 8 VCC, 9 VCC, 10 ~{Q7}, 11 Q7, 12 ~{Q6}, 13 Q6, 14 ~{Q5}, 15 Q5, 16 VCC, 17 GND, 18 VCC, 19 ~{Q4}, 20 Q4, 21 ~{Q3}, 22 Q3, 23 VCC, 24 GND, 25 VCC, 26 ~{Q2}, 27 Q2, 28 ~{Q1}, 29 Q1, 30 ~{Q0}, 31 Q0, 32 VCC, 33 GND

## SY89321LMG(LVPECL-LVTTL)
designator FF?
IC TRANSLATOR LVPECL-LVTTL 8-MLF; Manufacturer: Micrel Inc.; Manufacturer part #: SY89321LMG TR
footprint DFN_8PIN (DFN, 8-Leads, Body 2.00x2.00mm, Pitch 0.50mm, Thermal Pad 1.55x1.55mm, IPC Medium Density)
pins: 1 NC "CLOCK INPUT", 2 IN "INPUT", 3 ~{IN} "INPUT", 4 VBB "REFERANCE", 5 VEE "GROUND", 6 NC, 7 Q "LVTTL OUTPUT", 8 VCC "POWER", 9 GND "POWER"

## SY89854UMG(1-4 LVPECL-LVPECL)
designator FO?
IC CLK BUFFER 1:4 3.5GHZ 16MLF; Manufacturer: Micrel Inc.
footprint VFQFN_16PIN (QFN, 16-Leads, Body 3.00x3.00mm, Pitch 0.50mm, Thermal Pad 1.55x1.55mm, IPC Medium Density)
pins: 1 IN "Differential Inputs", 2 VT "Input Termination Center", 3 VREF "Reference Voltage:", 4 ~{IN} "Differential Inputs", 5 GND "INPUT", 6 ~{Q3} "Differential 100K LVPECL Outputs", 7 Q3 "Differential 100K LVPECL Outputs", 8 VCC "Positive Power Supply", 9 ~{Q2} "Differential 100K LVPECL Outputs", 10 Q2 "Differential 100K LVPECL Outputs", 11 ~{Q1} "Differential 100K LVPECL Outputs", 12 Q1 "Differential 100K LVPECL Outputs", 13 VCC "Positive Power Supply", 14 ~{Q0} "Differential 100K LVPECL Outputs", 15 Q0 "Differential 100K LVPECL Outputs", 16 GND "INPUT", 17 GND "INPUT"

## Test point
designator TP?
TEST POINT PC MINI .040"D BLACK; Manufacturer: Keystone Electronics; Manufacturer part #: 5001
footprint Test Point (TEST POINT PC MINI .040"D BLACK)
pins: 1 TP "test point"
